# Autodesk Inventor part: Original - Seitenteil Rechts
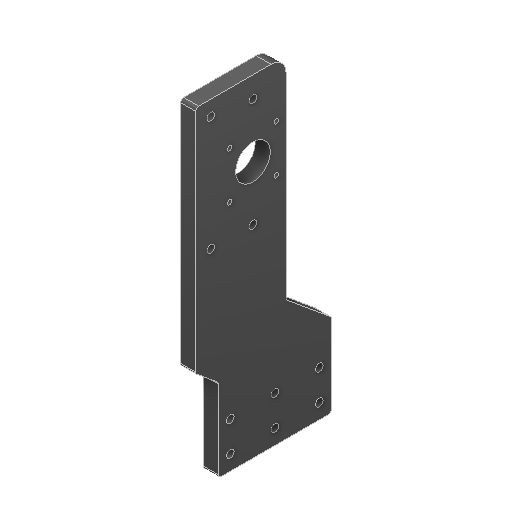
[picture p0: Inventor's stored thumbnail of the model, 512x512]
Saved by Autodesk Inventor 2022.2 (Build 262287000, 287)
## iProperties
Created: 2024-09
Part Number: Original - Seitenteil Rechts
Material: Generico
Document SubType Name: Modeling
Designer: 18907419
Density: 1 g/cm^3
Appearance: Default
Author: 18907419
Revision Number: ANY
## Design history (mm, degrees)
feature "Schnitt-Linear austragen1"
node "Solido1"
